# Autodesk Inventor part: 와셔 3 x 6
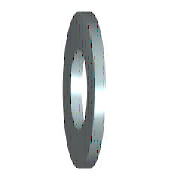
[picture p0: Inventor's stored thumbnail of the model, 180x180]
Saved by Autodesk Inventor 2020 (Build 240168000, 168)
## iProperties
Created: 2012-02
Part Number: 와셔 3 x 6
Material: 강철, 연강
Description: 평면 와셔
Document SubType Name: Modeling
Standard: KS B 1326
Designer: mduedu
Standards Organization: KS
Language: ko-KR
Size Designation: 3x6
Categories: <MemberInstance><Categories><Category DisplayName="조임쇠" InternalName="e4da775c-781d-43d5-af7c-5136215cf5a6" Mnemonic="FSTN"><Category DisplayName="와셔" InternalN
Density: 7.86 g/cm^3
Mass: 0.0795112 g
Surface Area: 0.54915 cm^2
Volume: 0.0101159 cm^3
Appearance: 파란색 - 벽 페인트 - 광택
IsCustomPart: 0
Author: mduedu
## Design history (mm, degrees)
sketch "스케치"
  geometry: C1 r 3 at (0, 0); C2 r 1.6 at (0, 0); 1 further point
  constraints: 2 centre point, 2 coincident
  dimensions: "d0" = 3.2 diameter of C2 (= SD1); "d1" = 6 diameter of C1 (= SD2)
extrude "본체" new body sketch "스케치" distance "d2" = 0.5 (= SD); taper "d3" = 0 deg
workaxis "Work Axis1"
workplane "Work Plane1"
body "Solid1"
other parameters: "SD1" = 3.2 [user parameter; used in 1 equation term], "SD2" = 6 [user parameter; used in 1 equation term], "SD" = 0.5 [user parameter; used in 1 equation term], "d4" = 0, "d5" = 0, "d6" = 0, "d7" = 0, "NND" = 3 [user parameter]
